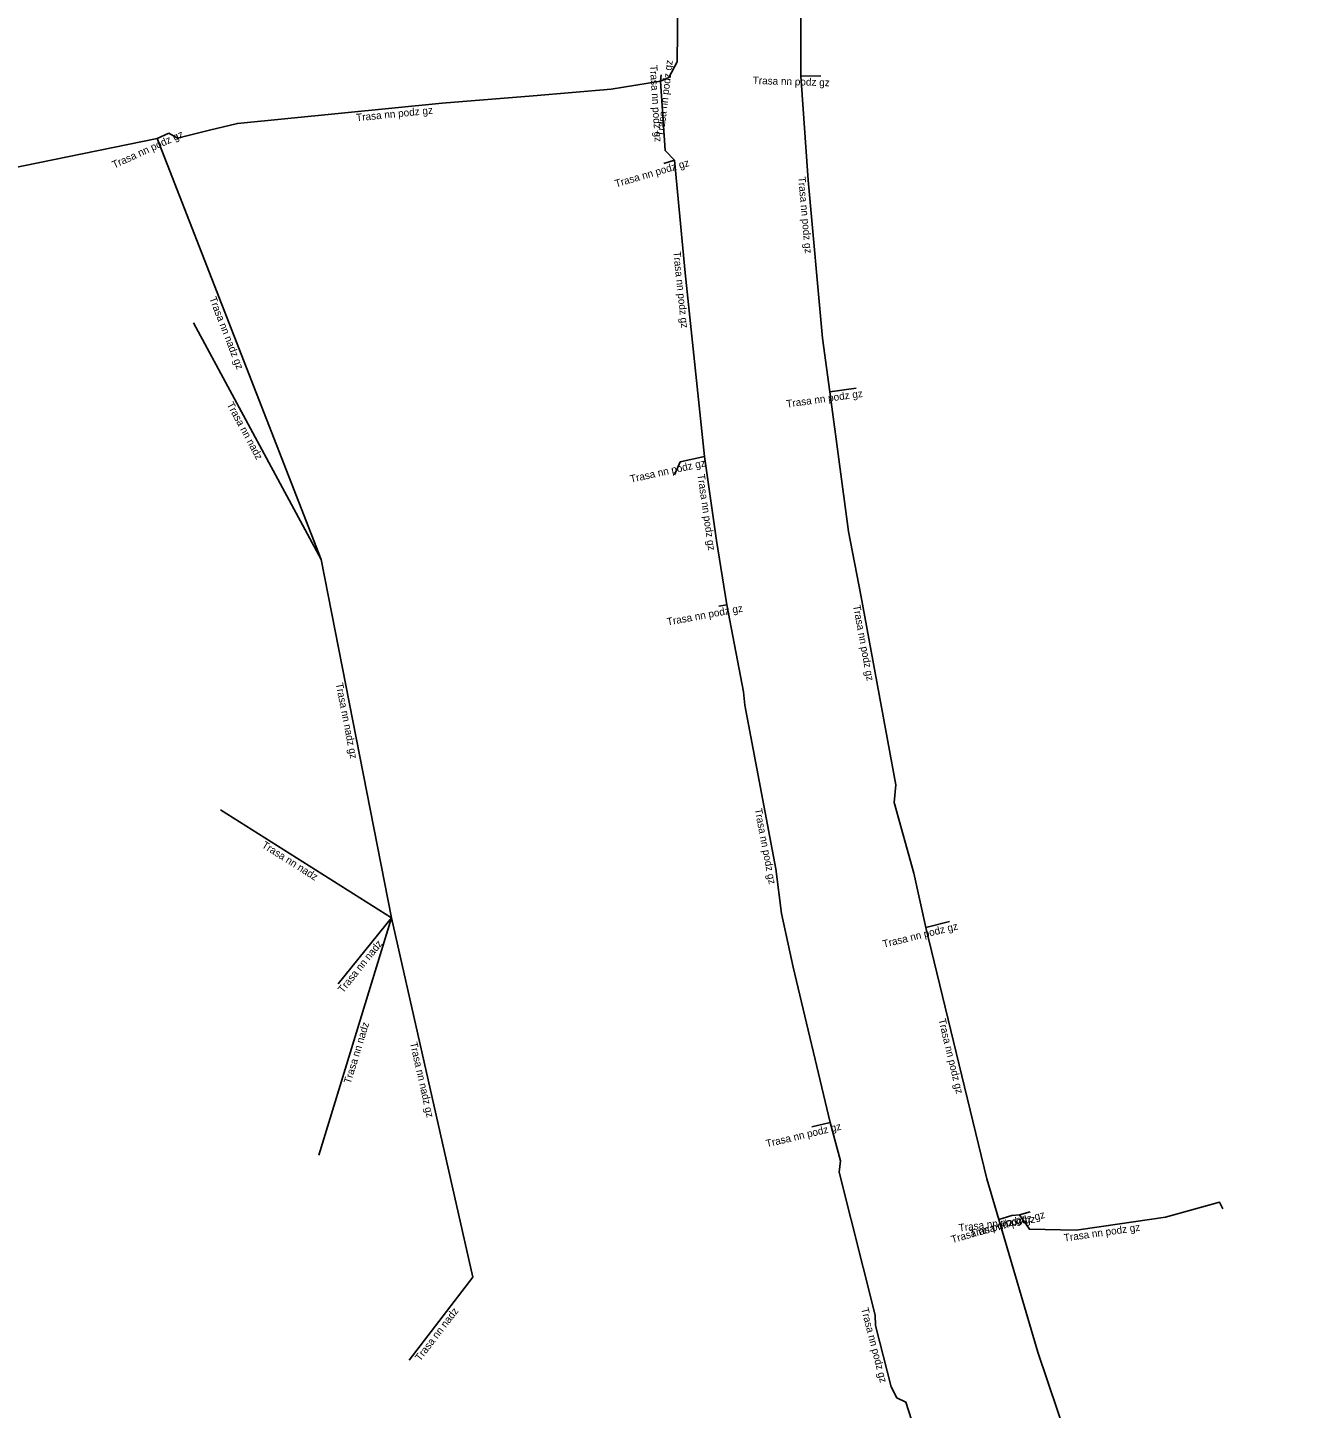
# Model space of a CAD drawing. Extents: x -660151 to -659156, y -1008082 to -1007440.
# Drawn here: x -660014.7 to -659928.5, y -1007756.3 to -1007663.7 of the extents above; entities that cross this region are included whole.
import ezdxf

# ---------------------------------------------------------------- set-up
doc = ezdxf.new("R2010")
doc.units = 0
doc.layers.add('Popiskový text - Ostatní atributy Trasy', color=7, linetype='Continuous')
doc.layers.add('Spojnice NN', color=7, linetype='Continuous')

msp = doc.modelspace()

# ---------------------------------------------------------------- linework, layer by layer
at = {"layer": 'Spojnice NN'}
for points in [[(-659962.86, -1007666.95), (-659962.9, -1007656.01), (-659962.48, -1007644.32), (-659962, -1007635.64)], [(-659972.27, -1007667.32), (-659971.72, -1007667.08), (-659971.15, -1007666.02), (-659971.06, -1007657.97), (-659970.98, -1007653.41), (-659972.67, -1007652.78), (-659973.11, -1007652.07), (-659973.88, -1007651.84), (-659974.43, -1007651.76)], [(-659972.27, -1007667.32), (-659972.22, -1007666.9)], [(-659972.27, -1007667.32), (-659975.59, -1007667.85), (-659980.81, -1007668.3), (-659986.91, -1007668.78), (-660000.63, -1007670.15), (-660002.51, -1007670.61), (-660004.66, -1007671.13), (-660005.24, -1007670.8)], [(-659971.34, -1007672.62), (-659971.97, -1007671.97), (-659972.27, -1007667.32)], [(-659960.93, -1007688.14), (-659961.42, -1007684.54), (-659962.38, -1007673.96), (-659962.86, -1007666.95)], [(-659962.86, -1007666.95), (-659961.52, -1007666.99)], [(-660044.93, -1007679.11), (-660006.01, -1007671.15)], [(-660006.01, -1007671.15), (-660005.24, -1007670.8)], [(-659995.02, -1007699.39), (-660006.01, -1007671.15)], [(-659971.34, -1007672.62), (-659972.06, -1007672.83)], [(-659969.32, -1007692.48), (-659970.62, -1007680.17), (-659971.34, -1007672.62)], [(-659995.02, -1007699.39), (-660003.582, -1007683.505)], [(-659960.93, -1007688.14), (-659959.15, -1007687.89)], [(-659954.48, -1007724.04), (-659955.29, -1007720.4), (-659956.62, -1007715.67), (-659956.49, -1007714.49), (-659958.84, -1007701.78), (-659959.67, -1007697.51), (-659960.93, -1007688.14)], [(-659969.32, -1007692.48), (-659970.95, -1007692.84), (-659971.34, -1007693.7)], [(-659967.82, -1007702.41), (-659968.51, -1007698.11), (-659969.32, -1007692.48)], [(-659990.31, -1007723.4), (-659995.02, -1007699.39)], [(-659967.82, -1007702.41), (-659968.36, -1007702.51)], [(-659960.9, -1007737.11), (-659963.38, -1007726.7), (-659964.17, -1007723.11), (-659964.54, -1007720.12), (-659966.63, -1007709.14), (-659966.71, -1007708.24), (-659967.82, -1007702.41)], [(-659990.31, -1007723.4), (-660001.773, -1007716.154)], [(-659990.31, -1007723.4), (-659995.183, -1007739.319)], [(-659990.31, -1007723.4), (-659993.874, -1007727.831)], [(-659984.85, -1007747.48), (-659990.31, -1007723.4)], [(-659954.48, -1007724.04), (-659952.9, -1007723.65)], [(-659949.6, -1007743.62), (-659950.4, -1007740.89), (-659954.48, -1007724.04)], [(-659960.9, -1007737.11), (-659962.12, -1007737.4)], [(-659951.49, -1007768.51), (-659952.93, -1007764.03), (-659954.06, -1007761.37), (-659955.82, -1007755.86), (-659956.44, -1007755.57), (-659956.81, -1007754.84), (-659957.87, -1007750.73), (-659957.89, -1007750.04), (-659960.3, -1007740.44), (-659960.22, -1007739.7), (-659960.9, -1007737.11)], [(-659948.21, -1007743.3), (-659947.55, -1007744.27), (-659944.42, -1007744.33), (-659942.72, -1007744.09), (-659938.42, -1007743.47), (-659934.8, -1007742.46), (-659934.58, -1007742.91)], [(-659949.6, -1007743.62), (-659948.72, -1007743.36)], [(-659928.51, -1007794.59), (-659929.38, -1007793.43), (-659933.44, -1007785.43), (-659936.32, -1007779.8), (-659940.12, -1007771.93), (-659942.94, -1007764.52), (-659946.99, -1007752.51), (-659949.6, -1007743.62)], [(-659948.72, -1007743.36), (-659948.21, -1007743.3)], [(-659948.21, -1007743.3), (-659947.5, -1007743.11)], [(-659989.122, -1007753.048), (-659984.85, -1007747.48)]]:
    msp.add_lwpolyline(points, dxfattribs=at)

# ---------------------------------------------------------------- texts
at = {"layer": 'Popiskový text - Ostatní atributy Trasy'}
for s, rotation, p in [('Trasa nn podz gz', 83.21103, (-659972.06, -1007671.053)), ('Trasa nn podz gz', 273.69139, (-659972.99, -1007666.252)), ('Trasa nn podz gz', 358.29019, (-659966.101, -1007667.504)), ('Trasa nn podz gz', 5.70232, (-659992.652, -1007670.007)), ('Trasa nn podz gz', 24.44395, (-660008.9, -1007673.178)), ('Trasa nn podz gz', 16.2602, (-659975.256, -1007674.439)), ('Trasa nn podz gz', 275.18466, (-659963.053, -1007673.741)), ('Trasa nn podz gz', 276.02839, (-659971.424, -1007678.75)), ('Trasa nn nadz gz', 291.26421, (-660002.533, -1007681.877)), ('Trasa nn podz gz', 7.99486, (-659963.805, -1007689.2)), ('Trasa nn nadz', 298.32463, (-660001.367, -1007688.985)), ('Trasa nn podz gz', 12.45435, (-659974.258, -1007694.236)), ('Trasa nn podz gz', 278.18708, (-659969.803, -1007693.689)), ('Trasa nn podz gz', 10.49148, (-659971.8, -1007703.808)), ('Trasa nn podz gz', 280.47533, (-659959.374, -1007702.471)), ('Trasa nn nadz gz', 281.09868, (-659994.053, -1007707.699)), ('Trasa nn podz gz', 280.7771, (-659965.965, -1007716.11)), ('Trasa nn nadz', 327.70217, (-659999.049, -1007718.644)), ('Trasa nn podz gz', 13.86547, (-659957.314, -1007725.409)), ('Trasa nn nadz', 51.18913, (-659993.558, -1007728.475)), ('Trasa nn nadz', 72.98001, (-659993.046, -1007734.56)), ('Trasa nn podz gz', 283.61142, (-659953.653, -1007730.216)), ('Trasa nn nadz gz', 282.77547, (-659989.075, -1007731.786)), ('Trasa nn podz gz', 13.37133, (-659965.147, -1007738.788)), ('Trasa nn podz gz', 16.46001, (-659952.71, -1007745.217)), ('Trasa nn podz gz', 6.70984, (-659952.256, -1007744.43)), ('Trasa nn podz gz', 14.98163, (-659951.449, -1007744.839)), ('Trasa nn podz gz', 8.20471, (-659945.203, -1007745.105)), ('Trasa nn nadz', 52.50309, (-659988.387, -1007753.156)), ('Trasa nn podz gz', 284.46186, (-659958.832, -1007749.599))]:
    msp.add_text(s, height=0.5, rotation=rotation, dxfattribs=at).set_placement(p)

doc.saveas('drawing.dxf')
